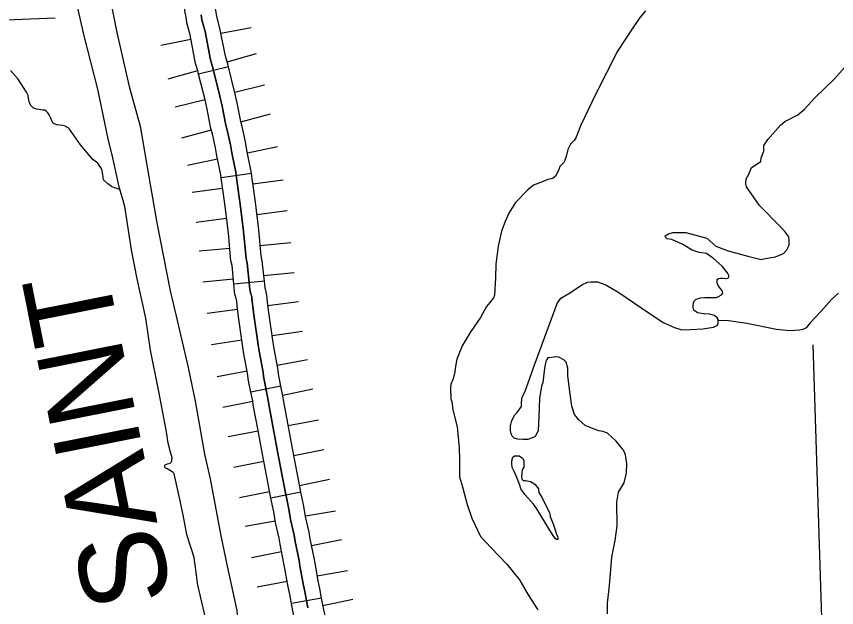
# Model space of a CAD drawing. Extents: x 1720274 to 1751788, y 372074 to 391887.
# Drawn here: x 1732879 to 1733514, y 374830 to 375288 of the extents above; entities that cross this region are included whole.
import ezdxf

# ---------------------------------------------------------------- set-up
doc = ezdxf.new("R2010")
doc.units = 0
for name, color, linetype in [('Level 29', 7, 'Continuous'), ('Level 32', 7, 'Continuous'), ('Level 35', 7, 'Continuous'), ('Level 5', 7, 'Continuous')]:
    doc.layers.add(name, color=color, linetype=linetype)

msp = doc.modelspace()

# ---------------------------------------------------------------- linework, layer by layer
at = {"layer": 'Level 29'}
for p, q in [((1733037.66, 375274.73), (1733060.93, 375279.26)), ((1733037.66, 375274.73), (1733060.93, 375279.26)), ((1732991.14, 375265.67), (1733014.4, 375270.2)), ((1732991.14, 375265.67), (1733014.4, 375270.2)), ((1733042.39, 375252.6), (1733065.16, 375259.17)), ((1732996.85, 375239.45), (1733019.62, 375246.02)), ((1733048.28, 375229.19), (1733071.28, 375234.92)), ((1733002.29, 375217.73), (1733025.29, 375223.46)), ((1733053.05, 375206.26), (1733075.91, 375212.51)), ((1733053.05, 375206.26), (1733075.91, 375212.51)), ((1733007.33, 375193.75), (1733030.19, 375200)), ((1733007.33, 375193.75), (1733030.19, 375200)), ((1733058.16, 375182.34), (1733081.38, 375187.09)), ((1733011.72, 375172.83), (1733034.94, 375177.58)), ((1733062.36, 375158.23), (1733085.84, 375161.45)), ((1733015.4, 375151.79), (1733038.88, 375155.01)), ((1733065.49, 375134.6), (1733089, 375137.53)), ((1733065.49, 375134.6), (1733089, 375137.53)), ((1733018.45, 375128.72), (1733041.97, 375131.66)), ((1733018.45, 375128.72), (1733041.97, 375131.66)), ((1733068.08, 375110.65), (1733091.68, 375112.82)), ((1733020.88, 375106.32), (1733044.48, 375108.49)), ((1733023.66, 375082.48), (1733047.24, 375084.86)), ((1733070.82, 375087.24), (1733094.4, 375089.62)), ((1733074.05, 375064.12), (1733097.56, 375067.09)), ((1733074.05, 375064.12), (1733097.56, 375067.09)), ((1733027.02, 375058.19), (1733050.54, 375061.16)), ((1733027.02, 375058.19), (1733050.54, 375061.16)), ((1733077.33, 375040.88), (1733100.78, 375044.29)), ((1733030.42, 375034.05), (1733053.87, 375037.47)), ((1733081.22, 375018), (1733104.52, 375022.38)), ((1733034.64, 375009.24), (1733057.93, 375013.62)), ((1733085.46, 374994.86), (1733108.69, 374999.56)), ((1733085.46, 374994.86), (1733108.69, 374999.56)), ((1733039, 374985.47), (1733062.23, 374990.16)), ((1733039, 374985.47), (1733062.23, 374990.16)), ((1733089.71, 374971.33), (1733113.02, 374975.6)), ((1733043.09, 374962.79), (1733066.4, 374967.06)), ((1733094.01, 374948.14), (1733117.28, 374952.65)), ((1733047.48, 374939.13), (1733070.74, 374943.64)), ((1733098.51, 374924.96), (1733121.75, 374929.62)), ((1733098.51, 374924.96), (1733121.75, 374929.62)), ((1733052.04, 374915.62), (1733075.28, 374920.29)), ((1733052.04, 374915.62), (1733075.28, 374920.29)), ((1733103.02, 374901.31), (1733126.39, 374905.25)), ((1733056.28, 374893.44), (1733079.65, 374897.38)), ((1733107.81, 374878.46), (1733131.06, 374883.06)), ((1733061.31, 374869.25), (1733084.56, 374873.85)), ((1733112.23, 374854.97), (1733135.55, 374859.18)), ((1733112.23, 374854.97), (1733135.55, 374859.18)), ((1733065.58, 374846.55), (1733088.91, 374850.76)), ((1733065.58, 374846.55), (1733088.91, 374850.76)), ((1733116.59, 374831.97), (1733139.81, 374836.76))]:
    msp.add_line(p, q, dxfattribs=at)
msp.add_lwpolyline([(1733022.29, 375289.13), (1733022.94, 375285.22), (1733025.31, 375276.17), (1733029.58, 375254.24), (1733031.39, 375247.96), (1733036.87, 375225.99), (1733038.63, 375218.46), (1733041.46, 375203.69), (1733042.53, 375199.78), (1733044.95, 375188.4), (1733046.11, 375182.13), (1733049.17, 375167.17), (1733050.28, 375159.08), (1733052.56, 375142.5), (1733055.2, 375121.31), (1733057.11, 375100.59), (1733057.94, 375096.83), (1733059.71, 375079.36), (1733059.99, 375076.11), (1733060.12, 375075.13), (1733060.4, 375074.06), (1733060.77, 375072.99), (1733061.15, 375071.79), (1733061.42, 375070.35), (1733061.61, 375068.81), (1733061.93, 375065.47), (1733063, 375057.01), (1733066.39, 375033.73), (1733067.13, 375028.81), (1733069.97, 375013.76), (1733070.75, 375007.81), (1733073.91, 374992.2), (1733074.33, 374989.13), (1733077.76, 374970.78), (1733081.34, 374951.27), (1733086.54, 374924.41), (1733090.11, 374906.62), (1733091.46, 374898.63), (1733094.29, 374886.36), (1733095.12, 374881.53), (1733098.05, 374866.76), (1733098.79, 374862.71), (1733101.3, 374848.82), (1733102.64, 374842.83), (1733104.87, 374830.14)], dxfattribs=at)
at = {"layer": 'Level 32'}
for p, q in [((1733043.37, 375248.9), (1733020.37, 375243.17)), ((1733061.27, 375166.16), (1733037.79, 375162.92)), ((1733071.26, 375082.93), (1733047.68, 375080.55)), ((1733084.07, 375001.76), (1733060.84, 374997.07)), ((1733099.55, 374919.78), (1733076.32, 374915.11)), ((1733115.59, 374837.63), (1733092.24, 374833.53))]:
    msp.add_line(p, q, dxfattribs=at)
for points in [[(1733020.37, 375243.17), (1733019.95, 375244.89), (1733018.05, 375251.45), (1733013.75, 375273.53), (1733011.34, 375282.75), (1733010.61, 375287.13), (1733009.74, 375292.11), (1733009.5, 375294.98), (1733007.65, 375307.08), (1733007.31, 375310.59), (1733007.07, 375315.86), (1733006.36, 375327.39)], [(1733043.37, 375248.9), (1733042.84, 375251.04), (1733041.11, 375257.02), (1733036.87, 375278.8), (1733034.54, 375287.7), (1733033.98, 375291.12), (1733033.27, 375295.16), (1733033.05, 375297.77), (1733031.18, 375310.01), (1733030.96, 375312.27), (1733030.74, 375317.13), (1733030.02, 375328.84)], [(1733104.87, 374830.14), (1733102.64, 374842.83), (1733101.3, 374848.82), (1733098.79, 374862.71), (1733098.05, 374866.76), (1733095.12, 374881.53), (1733094.29, 374886.36), (1733091.46, 374898.63), (1733090.11, 374906.62), (1733086.54, 374924.41), (1733081.34, 374951.27), (1733077.76, 374970.78), (1733074.33, 374989.13), (1733073.91, 374992.2), (1733070.75, 375007.81), (1733069.97, 375013.76), (1733067.13, 375028.81), (1733066.39, 375033.73), (1733063, 375057.01), (1733061.93, 375065.47), (1733061.61, 375068.81), (1733061.42, 375070.35), (1733061.15, 375071.79), (1733060.77, 375072.99), (1733060.4, 375074.06), (1733060.12, 375075.13), (1733059.99, 375076.11), (1733059.71, 375079.36), (1733057.94, 375096.83), (1733057.11, 375100.59), (1733055.2, 375121.31), (1733052.56, 375142.5), (1733050.28, 375159.08), (1733049.17, 375167.17), (1733046.11, 375182.13), (1733044.95, 375188.4), (1733042.53, 375199.78), (1733041.46, 375203.69), (1733038.63, 375218.46), (1733036.87, 375225.99), (1733031.39, 375247.96), (1733029.58, 375254.24), (1733025.31, 375276.17), (1733022.94, 375285.22), (1733022.29, 375289.13)], [(1733037.79, 375162.92), (1733037.48, 375165.17), (1733034.47, 375179.86), (1733033.32, 375186.09), (1733031.01, 375196.99), (1733029.91, 375201), (1733027.04, 375215.99), (1733025.35, 375223.2), (1733020.37, 375243.17)], [(1733061.27, 375166.16), (1733060.86, 375169.17), (1733057.74, 375184.4), (1733056.57, 375190.71), (1733054.05, 375202.58), (1733053.02, 375206.37), (1733050.23, 375220.93), (1733048.39, 375228.77), (1733043.37, 375248.9)], [(1733047.68, 375080.55), (1733046.22, 375094.94), (1733045.38, 375098.76), (1733043.42, 375120.04), (1733040.81, 375140.96), (1733038.54, 375157.47), (1733037.79, 375162.92)], [(1733071.26, 375082.93), (1733069.66, 375098.71), (1733068.84, 375102.42), (1733066.99, 375122.59), (1733064.31, 375144.04), (1733062.02, 375160.7), (1733061.27, 375166.16)], [(1733060.84, 374997.07), (1733059.06, 375005.85), (1733058.26, 375011.88), (1733055.45, 375026.83), (1733054.67, 375032), (1733051.26, 375055.42), (1733050.16, 375064.15), (1733049.83, 375067.53), (1733049.71, 375068.51), (1733049.63, 375068.91), (1733049.51, 375069.31), (1733049.06, 375070.62), (1733048.49, 375072.79), (1733048.21, 375074.76), (1733047.91, 375078.26), (1733047.68, 375080.55)], [(1733084.07, 375001.76), (1733082.45, 375009.77), (1733081.67, 375015.63), (1733078.82, 375030.79), (1733078.11, 375035.47), (1733074.74, 375058.61), (1733073.71, 375066.78), (1733073.39, 375070.1), (1733073.14, 375072.19), (1733072.66, 375074.66), (1733072.04, 375076.68), (1733071.76, 375077.48), (1733071.51, 375080.46), (1733071.26, 375082.93)], [(1733076.32, 374915.11), (1733074.91, 374922.12), (1733069.69, 374949.07), (1733066.11, 374968.62), (1733062.63, 374987.24), (1733062.22, 374990.22), (1733060.84, 374997.07)], [(1733099.55, 374919.78), (1733098.16, 374926.71), (1733092.98, 374953.46), (1733089.42, 374972.94), (1733086.03, 374991.02), (1733085.6, 374994.18), (1733084.07, 375001.76)], [(1733115.59, 374837.63), (1733114.27, 374845.15), (1733112.91, 374851.17), (1733110.45, 374864.84), (1733109.69, 374868.98), (1733106.78, 374883.69), (1733105.91, 374888.71), (1733103.08, 374900.95), (1733101.76, 374908.77), (1733099.55, 374919.78)], [(1733092.24, 374833.53), (1733091.02, 374840.5), (1733089.68, 374846.47), (1733087.13, 374860.59), (1733086.41, 374864.53), (1733083.47, 374879.37), (1733082.67, 374884.02), (1733079.83, 374896.31), (1733078.46, 374904.47), (1733076.32, 374915.11)], [(1733126, 374752.06), (1733126.32, 374755.73), (1733126.47, 374763.26), (1733125.79, 374777.52), (1733124.83, 374787.42), (1733123.92, 374792.41), (1733123.1, 374795.51), (1733122.38, 374799.66), (1733121.49, 374805.81), (1733118.69, 374821.77), (1733116.51, 374832.37), (1733115.59, 374837.63)], [(1733102.39, 374754.11), (1733102.64, 374757), (1733102.76, 374762.94), (1733102.15, 374775.81), (1733101.34, 374784.13), (1733100.77, 374787.23), (1733099.92, 374790.45), (1733098.97, 374795.95), (1733098.09, 374802.07), (1733095.41, 374817.33), (1733093.23, 374827.92), (1733092.24, 374833.53)]]:
    msp.add_lwpolyline(points, dxfattribs=at)
at = {"layer": 'Level 35'}
for points in [[(1732949.38, 375314.56), (1732957.05, 375275.29), (1732966.64, 375233.58), (1732975.01, 375202.87), (1732981.81, 375163.6), (1732988.09, 375128.17), (1732998.37, 375075.47), (1733003.08, 375055.92), (1733012.32, 375016.13), (1733017.73, 374990.13), (1733024.87, 374949.11), (1733029.23, 374929.92), (1733037.6, 374885.76), (1733042.48, 374862.38), (1733049.81, 374828.17), (1733052.25, 374803.04), (1733053.64, 374789.25), (1733057.3, 374760.63), (1733059.92, 374742.48), (1733061.11, 374723.78)], [(1733026.86, 374816.99), (1733019.72, 374847.72), (1733016.83, 374869.02), (1733015.46, 374874.04), (1733013.49, 374879.36), (1733011.21, 374886.97), (1733008.32, 374902.18), (1733005.58, 374915.26), (1733001.48, 374933.82), (1733001.26, 374934.48), (1733000.77, 374934.88), (1732999.75, 374935.41), (1732995.99, 374937.63), (1732994.57, 374938.56), (1732994.26, 374938.96), (1732994.21, 374939.27), (1732994.21, 374939.67), (1732994.3, 374940.33), (1732994.57, 374940.77), (1732995.06, 374941.17), (1732996.16, 374941.62), (1732998.38, 374942.15), (1732999.18, 374942.81), (1732999.71, 374944.01), (1732999.84, 374946.23), (1732998.69, 374950.71), (1732996.83, 374957.58), (1732995.5, 374966.46), (1732989.47, 374997.5), (1732983.09, 375029.44), (1732979.37, 375054.28), (1732972.81, 375084.79), (1732968.38, 375107.14), (1732963.24, 375140.68), (1732958.95, 375155.95), (1732953.52, 375180.75), (1732950.58, 375191.85), (1732942.43, 375231.5), (1732931.79, 375272.73), (1732925.46, 375299.91)], [(1733366.31, 375292.17), (1733362.01, 375287.19), (1733356.35, 375279.04), (1733344.59, 375260.93), (1733327.63, 375227.42), (1733316.32, 375203.65), (1733312.7, 375194.37), (1733311.12, 375191.88), (1733308.18, 375188.94), (1733306.14, 375184.86), (1733304.79, 375179.43), (1733303.2, 375174.9), (1733300.04, 375171.73), (1733298.91, 375168.56), (1733296.64, 375164.26), (1733294.61, 375162.45), (1733290.76, 375161.54), (1733286.92, 375160.19), (1733279.68, 375157.24), (1733275.16, 375153.62), (1733265.66, 375143.89), (1733260.46, 375135.51), (1733257.52, 375129.17), (1733254.8, 375121.7), (1733252.09, 375110.15), (1733250.51, 375096.12), (1733250.05, 375085.48), (1733249.37, 375072.12), (1733248.47, 375070.08), (1733245.76, 375066.46), (1733243.27, 375063.29), (1733238.52, 375054.92), (1733230.6, 375043.14), (1733224.27, 375032.96), (1733220.2, 375022.54), (1733219.07, 375017.11), (1733218.61, 375012.81), (1733217.26, 375007.37), (1733215.45, 375003.3), (1733215.22, 374999.9), (1733215.67, 374991.98), (1733216.58, 374988.81), (1733216.81, 374984.51), (1733220.42, 374970.25), (1733222.01, 374953.95), (1733222.23, 374944.89), (1733222.23, 374931.53), (1733224.5, 374923.84), (1733228.11, 374910.25), (1733231.73, 374899.61), (1733238.52, 374885.35), (1733246.89, 374876.52), (1733258.87, 374863.84), (1733268.83, 374851.84), (1733275.38, 374840.3), (1733282.85, 374828.75)], [(1733444.34, 375155.88), (1733443.88, 375158.15), (1733444.11, 375162.22), (1733446.15, 375165.62), (1733448.41, 375170.83), (1733455.42, 375175.58), (1733455.87, 375178.3), (1733457.91, 375183.5), (1733457.91, 375188.03), (1733461.07, 375192.56), (1733470.8, 375203.65), (1733474.19, 375206.37), (1733484.14, 375211.58), (1733489.34, 375216.1), (1733497.26, 375224.93), (1733512.64, 375239.42), (1733526.21, 375255.04)], [(1732959.82, 375153.65), (1732957.16, 375154.65), (1732955.33, 375155.15), (1732953, 375156.31), (1732950, 375158.15), (1732946.84, 375161.31), (1732946.17, 375165.48), (1732945.5, 375169.65), (1732943.84, 375171.98), (1732942.34, 375174.14), (1732938.51, 375176.98), (1732929.02, 375188.31), (1732921.69, 375198.81), (1732920.53, 375200.64), (1732919.36, 375201.64), (1732917.86, 375202.48), (1732917.2, 375202.81), (1732915.37, 375203.48), (1732912.37, 375203.64), (1732910.54, 375203.98), (1732909.37, 375204.31), (1732907.71, 375205.31), (1732906.71, 375206.98), (1732905.88, 375208.98), (1732905.38, 375210.14), (1732904.54, 375211.64), (1732903.71, 375213.14), (1732902.55, 375214.14), (1732901.21, 375215.14), (1732899.72, 375215.31), (1732898.22, 375215.64), (1732895.22, 375215.98), (1732893.22, 375216.48), (1732892.22, 375217.14), (1732890.72, 375218.64), (1732889.56, 375220.98), (1732888.56, 375224.31), (1732888.39, 375226.48), (1732887.23, 375229.31), (1732884.9, 375232.81), (1732880.73, 375239.14), (1732874.74, 375245.98)], [(1733278.1, 374961.42), (1733275.16, 374960.51), (1733271.31, 374960.51), (1733267.47, 374960.74), (1733264.53, 374961.42), (1733262.94, 374963), (1733262.27, 374965.04), (1733261.81, 374967.08), (1733261.81, 374970.7), (1733262.49, 374974.32), (1733264.98, 374979.3), (1733266.79, 374981.34), (1733270.18, 374985.87), (1733270.18, 374989.26), (1733270.86, 374993.11), (1733272.9, 374996.96), (1733276.74, 375007.83), (1733280.13, 375017.33), (1733298, 375065.56), (1733300.72, 375069.86), (1733306.82, 375073.48), (1733312.02, 375076.65), (1733317, 375080.04), (1733321.3, 375082.08), (1733324.01, 375082.53), (1733328.99, 375082.53), (1733335.55, 375080.04), (1733345.72, 375074.16), (1733363.37, 375062.16), (1733379.88, 375051.07), (1733388.7, 375046.99), (1733394.35, 375045.41), (1733401.14, 375045.63), (1733410.64, 375046.09), (1733419, 375047.44), (1733421.94, 375048.8), (1733422.62, 375050.16), (1733422.62, 375051.97), (1733422.4, 375053.33), (1733421.72, 375054.46), (1733419.68, 375056.27), (1733415.84, 375057.41), (1733411.77, 375057.63), (1733411.09, 375057.63), (1733406.56, 375058.54), (1733403.62, 375060.57), (1733403.17, 375062.61), (1733403.17, 375064.42), (1733403.62, 375067.14), (1733405.43, 375068.95), (1733408.83, 375070.08), (1733412.22, 375070.31), (1733416.06, 375070.31), (1733419.23, 375070.31), (1733421.27, 375070.31), (1733422.85, 375070.99), (1733425.11, 375072.35), (1733426.02, 375073.71), (1733425.56, 375075.74), (1733423.75, 375077.78), (1733422.4, 375079.59), (1733421.72, 375081.4), (1733421.72, 375082.76), (1733421.72, 375084.12), (1733422.85, 375085.02), (1733424.43, 375085.25), (1733426.24, 375085.25), (1733428.28, 375085.02), (1733430.09, 375085.25), (1733430.77, 375085.93), (1733430.77, 375087.29), (1733429.63, 375089.33), (1733425.56, 375094.53), (1733419, 375100.42), (1733413.35, 375104.27), (1733407.92, 375105.17), (1733402.27, 375106.98), (1733395.26, 375111.29), (1733386.66, 375115.13), (1733383.04, 375115.81), (1733381.69, 375116.95), (1733381.46, 375118.08), (1733384.17, 375119.66), (1733387.34, 375120.57), (1733397.52, 375120.57), (1733413.8, 375116.27), (1733420.59, 375110.15), (1733430.31, 375106.53), (1733445.47, 375102.23), (1733455.87, 375099.74), (1733459.26, 375100.42), (1733466.95, 375101.78), (1733473.06, 375104.27), (1733475.77, 375107.21), (1733477.36, 375110.83), (1733477.58, 375114.23), (1733477.13, 375117.17), (1733474.19, 375121.25), (1733471.02, 375124.64), (1733454.51, 375141.62), (1733444.34, 375155.88)], [(1733515.55, 375073.69), (1733510.12, 375068.82), (1733501.89, 375059.46), (1733493.66, 375050.65), (1733490.67, 375046.91), (1733488.05, 375045.6), (1733485.8, 375045.04), (1733477.94, 375044.47), (1733467.65, 375045.6), (1733444.64, 375050.09), (1733430.61, 375052.34), (1733422.94, 375052.53)], [(1733336.9, 374825.58), (1733336.9, 374833.73), (1733338.49, 374847.54), (1733340.3, 374869.5), (1733342.78, 374882.18), (1733344.37, 374893.73), (1733344.14, 374911.84), (1733345.27, 374919.76), (1733349.8, 374926.78), (1733351.6, 374934.7), (1733351.83, 374941.72), (1733350.7, 374948.51), (1733349.34, 374952.13), (1733346.63, 374955.3), (1733343.46, 374959.15), (1733336.9, 374965.26), (1733333.28, 374966.62), (1733330.12, 374967.08), (1733327.4, 374968.21), (1733319.49, 374971.38), (1733314.74, 374975.68), (1733311.35, 374979.75), (1733309.31, 374986.32), (1733307.73, 374997.19), (1733306.14, 375009.86), (1733306.14, 375015.52), (1733304.79, 375020.28), (1733302.98, 375022.09), (1733299.13, 375024.13), (1733296.87, 375024.35), (1733293.7, 375023.9), (1733290.76, 375023.67), (1733289.86, 375022.31), (1733289.18, 375020.73), (1733288.05, 375015.75), (1733286.69, 375004.43), (1733285.79, 375001.71), (1733284.2, 374992.21), (1733283.75, 374977.94), (1733283.07, 374967.3), (1733282.17, 374965.04), (1733280.81, 374962.77), (1733278.1, 374961.42)]]:
    msp.add_lwpolyline(points, dxfattribs=at)
msp.add_lwpolyline([(1733288.33, 374910.99), (1733291.86, 374903.91), (1733292.5, 374900.73), (1733295.04, 374894.38), (1733297.39, 374887.3), (1733298.3, 374884.85), (1733298.48, 374883.49), (1733298.3, 374883.03), (1733298.03, 374882.94), (1733297.39, 374882.94), (1733296.4, 374883.85), (1733291.95, 374890.57), (1733282.25, 374906.82), (1733279.53, 374910.27), (1733273.09, 374917.62), (1733269.64, 374922.34), (1733269.1, 374925.06), (1733267.65, 374928.51), (1733266.2, 374932.32), (1733264.56, 374935.59), (1733263.11, 374938.86), (1733262.75, 374941.77), (1733262.75, 374943.94), (1733263.66, 374946.67), (1733264.75, 374947.76), (1733266.2, 374947.76), (1733268.56, 374947.76), (1733271.09, 374945.94), (1733272.18, 374944.13), (1733272.18, 374942.31), (1733272, 374939.04), (1733270.73, 374937.04), (1733270.55, 374934.32), (1733270.19, 374931.6), (1733270.73, 374929.6), (1733271.64, 374928.69), (1733273.45, 374928.69), (1733277.26, 374927.97), (1733280.53, 374925.79), (1733283.43, 374922.16), (1733283.61, 374919.43), (1733286.33, 374915.26)], close=True, dxfattribs=at)
at = {"layer": 'Level 5'}
for points in [[(1732662.47, 375276.62), (1732909.18, 375286.74)], [(1733495.85, 375033.75), (1733513.92, 374464.34)]]:
    msp.add_lwpolyline(points, dxfattribs=at)

# ---------------------------------------------------------------- texts
at = {"layer": 'Level 35'}
msp.add_text('SAINT', height=66.739, rotation=101.24844, dxfattribs=at).set_placement((1733000.16, 374837.4))

doc.saveas('drawing.dxf')
